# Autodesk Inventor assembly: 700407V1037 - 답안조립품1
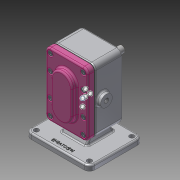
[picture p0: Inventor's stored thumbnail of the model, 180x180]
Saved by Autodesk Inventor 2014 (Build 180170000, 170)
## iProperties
Created: 2020-04
Part Number: 700407V1037 - 답안조립품1
Document SubType Name: Assembly
Designer: kh
Author: kh
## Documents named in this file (11)
- C:\Users\kh\Desktop\700407V1037\700407V1037 - 답안조립품1.iam
- C:\Users\kh\Desktop\700407V1037\700407V1037 - 본체.ipt
- C:\Users\kh\Desktop\700407V1037\개스킷.ipt
- C:\Users\kh\Desktop\700407V1037\메인축.ipt
- C:\Users\kh\Desktop\700407V1037\베어링부시.ipt
- C:\Users\kh\Desktop\700407V1037\볼트 M5.ipt
- C:\Users\kh\Desktop\700407V1037\서브축.ipt
- C:\Users\kh\Desktop\700407V1037\스퍼기어.ipt
- C:\Users\kh\Desktop\700407V1037\오일 실 16 28 7.ipt
- C:\Users\kh\Desktop\700407V1037\커버.ipt
- C:\Users\kh\Desktop\700407V1037\키 6 x 6 x 18.ipt
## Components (2 placed, 2 different names)
1. 700407V1037 - 본체:1 — 각도:2, 각도:3
2. 개스킷:1
## Component patterns: 구성요소 패턴 1:2 (2 elements), 구성요소 패턴 3:2 (2 elements)
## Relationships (2: Angle 2)
- 각도:2 [Angle]: 700407V1037 - 본체:1
- 각도:3 [Angle]: 700407V1037 - 본체:1
